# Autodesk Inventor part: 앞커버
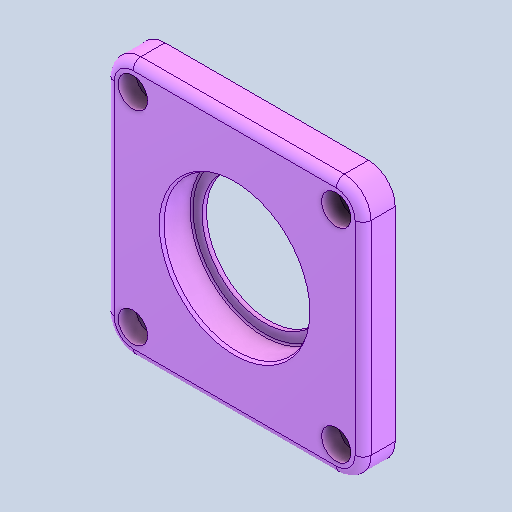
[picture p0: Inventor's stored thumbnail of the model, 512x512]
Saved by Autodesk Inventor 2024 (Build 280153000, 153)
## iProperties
Created: 2025-05
Part Number: 앞커버
Material: 알루미늄 6061
Document SubType Name: Modeling
Designer: 11
Density: 2.7 g/cm^3
Appearance: 기본값
Author: jhkim
Sending System: Autodesk Inventor 2026
Preprocessor: ST-DEVELOPER v20.1
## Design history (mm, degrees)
node "앞커버1"
node "솔리드2"
node "솔리드1"
